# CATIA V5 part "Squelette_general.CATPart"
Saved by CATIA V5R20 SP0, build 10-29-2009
Part number: Squelette_general
Publications: "B2g", "A1", "B1g", "B1d", "A2", "B2d", "b_2", "b_1", "C2", "C1", "pp_21", "pp_11", "pp_22", "pp_12", "pp_23", "pp_13", "Point.32", "Point.31", "Point.33", "Point.34", "Plan_base1", "Plan_socle", "Plan_horizontal_plateau2", "Plan_horizontal_plateau1", "plan_vertical_plateau2", "plan_vertical_plateau1", "plan_plateau2_bielle", "plan_plateau1_bielle", "plan_plateau2_support1", "plan_plateau1_support2", "Longueur_plateau", "h"
Bounding box of the stored display mesh (mm): x 0 to 100, y -400 to 400, z -250 to 100
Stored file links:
  C:\Users\Noëllie\Documents\IFMA\2A\S3\IAO\Projet Artobolevski\Catia\Squelette_general.CATPart
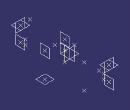
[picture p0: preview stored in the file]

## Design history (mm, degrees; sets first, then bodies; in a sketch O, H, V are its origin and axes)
Parameters
  Longueur_plateau = 350 mm
Body1 (main body)
  Point1 "B2g": (0, -50, 0)
  Point2 "A1": (100, -150, 0)
  Point3 "B1g": (100, -350, 0)
  Point4 "B1d": (100, 50, 0)
  Point5 "A2": (0, 150, 0)
  Point6 "B2d": (0, 350, 0)
  Point7 "b_2": (0, 150, -250)
  Point8 "b_1": (100, -150, -250)
  Point9 "C2": (0, 350, -50)
  Point10 "C1": (100, -350, -50)
  Point11 "pp_21": (100, 50, 100)
  Point12 "pp_11": (0, -50, 100)
  Point13 "pp_22": (-100, 350 {= Longueur_plateau}, 0), relative to Point11
  Point14 "pp_12": (100, -350 {= -Longueur_plateau}, 0), relative to Point12
  Point15 "pp_23": (0, 0, -150), relative to Point13
  Point16 "pp_13": (0, 0, -150), relative to Point14
  Point17: (-100, 0, 0), relative to Point11
  Point18: (0, 350 {= Longueur_plateau}, 0), relative to Point11
  Point19: (0, 350 {= Longueur_plateau}, 0), relative to Point14
  Point20: (-100, 0, 0), relative to Point14
  Plane1 "Plan_base1": type OffsetPt, RefPlane yz-plane, RefPoint Point2
  Plane2 "Plan_socle": type OffsetPt, RefPlane xy-plane, RefPoint Point8
  Plane3 "Plan_horizontal_plateau2": type OffsetPt, RefPlane xy-plane, RefPoint Point13
  Plane4 "Plan_horizontal_plateau1": type OffsetPt, RefPlane xy-plane, RefPoint Point14
  Plane5 "plan_vertical_plateau2": type OffsetPt, RefPlane zx-plane, RefPoint Point13
  Plane6 "plan_vertical_plateau1": type OffsetPt, RefPlane zx-plane, RefPoint Point14
  Plane7 "plan_plateau2_bielle": type OffsetPt, RefPlane yz-plane, RefPoint Point15
  Plane8 "plan_plateau1_bielle": type OffsetPt, RefPlane yz-plane, RefPoint Point16
  Plane9 "plan_plateau2_support1": type OffsetPt, RefPlane yz-plane, RefPoint Point11
  Plane10 "plan_plateau1_support2": type OffsetPt, RefPlane yz-plane, RefPoint Point12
